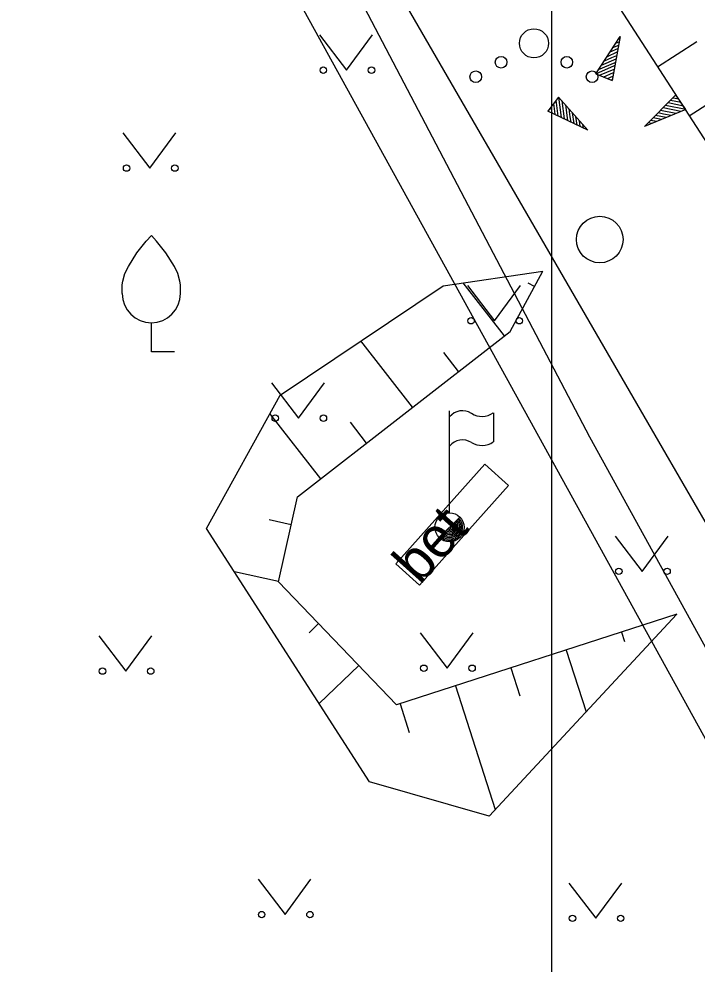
# Model space of a CAD drawing. Extents: x 554947 to 555436, y 6564938 to 6565792.
# Drawn here: x 555230.43 to 555242.09, y 6565114.23 to 6565130.48 of the extents above; entities that cross this region are included whole.
import ezdxf

# ---------------------------------------------------------------- set-up
doc = ezdxf.new("R2010")
doc.units = 0
for name, color, linetype in [('HALJASTUS', 7, 'Continuous'), ('MPKAABEL', 7, 'Continuous'), ('POST', 7, 'Continuous'), ('PR_SIDE', 7, 'Continuous'), ('PUU', 7, 'Continuous'), ('RAJATIS', 7, 'Continuous'), ('RELJEEF', 7, 'Continuous'), ('TEE', 7, 'Continuous'), ('VORMISTUS', 7, 'Continuous')]:
    doc.layers.add(name, color=color, linetype=linetype)

msp = doc.modelspace()

# ---------------------------------------------------------------- linework, layer by layer
at = {"layer": 'HALJASTUS'}
for p, q in [((555235.602, 6565130.2), (555236.066, 6565129.594)), ((555236.066, 6565129.594), (555236.511, 6565130.2)), ((555232.222, 6565128.518), (555232.685, 6565127.911)), ((555232.685, 6565127.911), (555233.131, 6565128.518)), ((555238.142, 6565125.893), (555238.605, 6565125.287)), ((555238.605, 6565125.287), (555239.051, 6565125.893)), ((555234.776, 6565124.22), (555235.24, 6565123.613)), ((555235.24, 6565123.613), (555235.685, 6565124.22)), ((555240.681, 6565121.586), (555241.145, 6565120.98)), ((555241.145, 6565120.98), (555241.59, 6565121.586)), ((555237.331, 6565119.921), (555237.794, 6565119.315)), ((555237.794, 6565119.315), (555238.24, 6565119.921)), ((555231.808, 6565119.872), (555232.271, 6565119.265)), ((555232.271, 6565119.265), (555232.717, 6565119.872)), ((555234.544, 6565115.687), (555235.007, 6565115.08)), ((555235.007, 6565115.08), (555235.453, 6565115.687)), ((555239.885, 6565115.623), (555240.349, 6565115.016)), ((555240.349, 6565115.016), (555240.794, 6565115.623))]:
    msp.add_line(p, q, dxfattribs=at)
msp.add_lwpolyline([(555235.12, 6565151.155), (555232.135, 6565148.949), (555229.151, 6565146.49), (555228.521, 6565144.196), (555233.66, 6565136.637), (555246.422, 6565114.586), (555255.514, 6565098.946)], dxfattribs=at)
for centre, radius in [((555239.285, 6565130.056), 0.25), ((555238.72, 6565129.731), 0.1), ((555239.85, 6565129.731), 0.1), ((555235.665, 6565129.594), 0.055), ((555236.493, 6565129.594), 0.055), ((555238.285, 6565129.481), 0.1), ((555240.285, 6565129.481), 0.1), ((555232.284, 6565127.911), 0.055), ((555233.113, 6565127.911), 0.055), ((555240.416, 6565126.683), 0.4), ((555238.204, 6565125.287), 0.055), ((555239.033, 6565125.287), 0.055), ((555234.839, 6565123.613), 0.055), ((555235.667, 6565123.613), 0.055), ((555240.744, 6565120.98), 0.055), ((555241.573, 6565120.98), 0.055), ((555231.87, 6565119.265), 0.055), ((555232.699, 6565119.265), 0.055), ((555237.393, 6565119.315), 0.055), ((555238.222, 6565119.315), 0.055), ((555234.606, 6565115.08), 0.055), ((555235.435, 6565115.08), 0.055), ((555239.948, 6565115.016), 0.055), ((555240.776, 6565115.016), 0.055)]:
    msp.add_circle(centre, radius, dxfattribs=at)
at = {"layer": 'MPKAABEL'}
msp.add_lwpolyline([(555252.588, 6565101.946), (555250.157, 6565105.485), (555246.43, 6565112.048), (555243.328, 6565117.686), (555240.248, 6565123.284), (555235.885, 6565131.607), (555233.393, 6565136.173), (555233.034, 6565137.981), (555233.62, 6565138.358), (555237.1, 6565137.907), (555242.704, 6565136.954), (555245.573, 6565136.455), (555256.506, 6565134.49), (555262.887, 6565133.288), (555269.268, 6565132.087), (555280.849, 6565129.896), (555289.168, 6565128.301), (555288.207, 6565123.189), (555286.959, 6565118.589), (555293.983, 6565117.646), (555297.167, 6565117.091)], dxfattribs=at)
at = {"layer": 'POST'}
msp.add_line((555237.657, 6565121.561), (555238.011, 6565121.914), dxfattribs=at)
msp.add_circle((555237.834, 6565121.737), 0.25, dxfattribs=at)
for radius, start, end in [(0.225, 224.8541, 45.0356), (0.2, 224.8427, 45.047), (0.175, 224.8281, 45.0616), (0.15, 224.8087, 45.081), (0.125, 224.7814, 45.1083), (0.1, 224.7406, 45.1491), (0.075, 224.6725, 45.2172), (0.05, 224.5363, 45.3534), (0.025, 224.1278, 45.7619)]:
    msp.add_arc((555237.834, 6565121.737), radius, start, end, dxfattribs=at)
at = {"layer": 'PR_SIDE'}
msp.add_lwpolyline([(555231.314, 6565137.915), (555250.156, 6565103.719), (555250, 6565102), (555221.076, 6565087.78)], dxfattribs=at)
at = {"layer": 'PUU'}
for p, q in [((555232.71, 6565124.753), (555232.71, 6565125.253)), ((555233.11, 6565124.753), (555232.71, 6565124.753))]:
    msp.add_line(p, q, dxfattribs=at)
for points in [[(555232.21, 6565125.753), (555232.21, 6565125.903), (555232.22, 6565125.968), (555232.255, 6565126.098), (555232.315, 6565126.218), (555232.46, 6565126.453), (555232.62, 6565126.658), (555232.71, 6565126.753)], [(555233.21, 6565125.753), (555233.21, 6565125.903), (555233.2, 6565125.968), (555233.165, 6565126.098), (555233.105, 6565126.218), (555232.96, 6565126.453), (555232.8, 6565126.658), (555232.71, 6565126.753)]]:
    msp.add_lwpolyline(points, dxfattribs=at)
msp.add_arc((555232.71, 6565125.753), 0.5, 180, 0, dxfattribs=at)
at = {"layer": 'RAJATIS'}
for p, q in [((555237.834, 6565121.987), (555237.834, 6565123.737)), ((555238.587, 6565123.706), (555238.587, 6565123.206)), ((555237.834, 6565121.737), (555237.834, 6565121.737))]:
    msp.add_line(p, q, dxfattribs=at)
for centre, radius, start, end in [((555238.057, 6565123.452), 0.288, 57.8941, 140.7366), ((555238.391, 6565123.985), 0.341, 237.8941, 305.0219), ((555238.057, 6565122.952), 0.288, 57.8941, 140.7366), ((555238.391, 6565123.485), 0.341, 237.8941, 305.0219)]:
    msp.add_arc(centre, radius, start, end, dxfattribs=at)
at = {"layer": 'RELJEEF'}
for p, q in [((555240.347, 6565129.532), (555240.767, 6565130.172)), ((555240.767, 6565130.172), (555240.627, 6565129.417)), ((555241.954, 6565128.812), (555244.214, 6565130.273)), ((555240.642, 6565129.982), (555240.742, 6565130.022)), ((555240.692, 6565130.057), (555240.752, 6565130.082)), ((555240.742, 6565130.132), (555240.762, 6565130.142)), ((555241.411, 6565129.652), (555242.087, 6565130.089)), ((555240.547, 6565129.832), (555240.717, 6565129.907)), ((555240.597, 6565129.907), (555240.727, 6565129.967)), ((555240.622, 6565129.812), (555240.707, 6565129.847)), ((555240.347, 6565129.532), (555240.672, 6565129.672)), ((555240.397, 6565129.607), (555240.682, 6565129.727)), ((555240.447, 6565129.682), (555240.697, 6565129.787)), ((555240.497, 6565129.757), (555240.622, 6565129.812)), ((555240.347, 6565129.532), (555240.627, 6565129.417)), ((555240.347, 6565129.532), (555240.347, 6565129.532)), ((555240.412, 6565129.507), (555240.662, 6565129.612)), ((555240.477, 6565129.477), (555240.652, 6565129.552)), ((555240.547, 6565129.452), (555240.642, 6565129.492)), ((555240.612, 6565129.427), (555240.627, 6565129.432)), ((555241.185, 6565128.626), (555241.725, 6565129.171)), ((555241.895, 6565128.921), (555241.725, 6565129.171)), ((555239.706, 6565129.131), (555239.521, 6565128.891)), ((555239.621, 6565129.021), (555239.646, 6565128.836)), ((555239.661, 6565129.076), (555239.696, 6565128.806)), ((555239.706, 6565129.131), (555240.211, 6565128.561)), ((555239.706, 6565129.131), (555239.751, 6565128.781)), ((555239.706, 6565129.131), (555239.706, 6565129.131)), ((555239.766, 6565129.066), (555239.806, 6565128.756)), ((555241.855, 6565128.976), (555241.59, 6565129.031)), ((555241.815, 6565129.036), (555241.63, 6565129.071)), ((555241.775, 6565129.096), (555241.675, 6565129.116)), ((555241.735, 6565129.156), (555241.715, 6565129.156)), ((555240.211, 6565128.561), (555239.521, 6565128.891)), ((555239.531, 6565128.906), (555239.536, 6565128.886)), ((555239.576, 6565128.961), (555239.591, 6565128.861)), ((555239.826, 6565128.996), (555239.861, 6565128.731)), ((555239.886, 6565128.931), (555239.901, 6565128.791)), ((555239.941, 6565128.861), (555239.971, 6565128.676)), ((555241.895, 6565128.921), (555241.185, 6565128.626)), ((555241.51, 6565128.841), (555241.42, 6565128.861)), ((555241.725, 6565128.851), (555241.46, 6565128.901)), ((555241.81, 6565128.886), (555241.505, 6565128.946)), ((555241.895, 6565128.921), (555241.545, 6565128.986)), ((555241.895, 6565128.921), (555241.895, 6565128.921)), ((555239.901, 6565128.791), (555239.916, 6565128.701)), ((555240.001, 6565128.796), (555240.021, 6565128.651)), ((555240.061, 6565128.726), (555240.076, 6565128.626)), ((555241.31, 6565128.676), (555241.25, 6565128.691)), ((555241.395, 6565128.711), (555241.29, 6565128.731)), ((555241.475, 6565128.746), (555241.335, 6565128.776)), ((555241.56, 6565128.781), (555241.375, 6565128.816)), ((555241.645, 6565128.816), (555241.51, 6565128.841)), ((555240.121, 6565128.661), (555240.131, 6565128.596)), ((555240.181, 6565128.591), (555240.186, 6565128.571)), ((555241.225, 6565128.641), (555241.21, 6565128.646)), ((555238.777, 6565125.027), (555238.069, 6565125.938)), ((555239.292, 6565125.874), (555239.185, 6565125.931)), ((555237.198, 6565123.8), (555236.311, 6565124.941)), ((555237.988, 6565124.414), (555237.735, 6565124.739)), ((555235.62, 6565122.572), (555234.747, 6565123.694)), ((555236.409, 6565123.186), (555236.13, 6565123.545)), ((555235.112, 6565121.78), (555234.732, 6565121.865)), ((555234.893, 6565120.804), (555234.136, 6565120.973)), ((555235.58, 6565120.081), (555235.419, 6565119.926)), ((555240.789, 6565119.935), (555240.84, 6565119.775)), ((555239.837, 6565119.627), (555240.181, 6565118.565)), ((555236.273, 6565119.361), (555235.594, 6565118.707)), ((555238.886, 6565119.319), (555239.04, 6565118.841)), ((555237.934, 6565119.011), (555238.621, 6565116.887)), ((555236.983, 6565118.704), (555237.142, 6565118.211))]:
    msp.add_line(p, q, dxfattribs=at)
for points in [[(555267.243, 6565100.718), (555264.574, 6565104.451), (555253.061, 6565121.25), (555242.65, 6565138.338), (555234.145, 6565148.829), (555233.386, 6565148.636), (555231.367, 6565148.23), (555230.85, 6565146.543), (555236.09, 6565137.882), (555248.799, 6565118.225), (555259.289, 6565103.411), (555261.934, 6565099.868)], [(555241.74, 6565120.242), (555238.516, 6565116.774), (555236.459, 6565117.362), (555233.657, 6565121.718), (555234.922, 6565124.01), (555237.725, 6565125.887), (555239.436, 6565126.14)], [(555241.74, 6565120.242), (555236.924, 6565118.685), (555234.892, 6565120.797), (555235.219, 6565122.261), (555238.876, 6565125.104), (555239.436, 6565126.14)]]:
    msp.add_lwpolyline(points, dxfattribs=at)
at = {"layer": 'TEE'}
msp.add_lwpolyline([(555238.44, 6565122.823), (555238.85, 6565122.456), (555237.32, 6565120.742), (555236.909, 6565121.109), (555238.44, 6565122.823)], dxfattribs=at)
at = {"layer": 'VORMISTUS'}
msp.add_lwpolyline([(555029.586, 6565234.913), (555239.586, 6565234.913), (555239.586, 6564937.913), (555029.586, 6564937.913)], close=True, dxfattribs=at)

# ---------------------------------------------------------------- texts
at = {"layer": 'TEE'}
msp.add_text('bet', height=0.7, rotation=48.2234, dxfattribs=at).set_placement((555237.325, 6565120.731))

doc.saveas('drawing.dxf')
